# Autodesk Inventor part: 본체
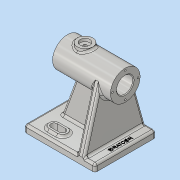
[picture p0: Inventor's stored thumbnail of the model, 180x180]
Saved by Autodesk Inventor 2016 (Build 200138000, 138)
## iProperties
Created: 2019-10
Part Number: 본체
Material: 알루미늄 6061
Document SubType Name: Modeling
Designer: Administrator
Density: 2.7 g/cm^3
Appearance: 알루미늄 - 평지
Mass: 588.046 g
Surface Area: 541.465 cm^2
Volume: 217.795 cm^3
Author: Administrator
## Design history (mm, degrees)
sketch "스케치1"
  geometry: L1 (-50, -43)-(50, -43); L2 (50, -43)-(50, 43); L3 (50, 43)-(-50, 43); L4 (-50, 43)-(-50, -43); L5 (-50, -43)-(50, 43); L6 (50, -43)-(-50, 43); 1 further point
  constraints: 12 end point, 2 midpoint, 2 parallel, 1 horizontal, 1 perpendicular
  dimensions: "d0" = 100 distance of L3.end L2.end; "d1" = 86 distance of L2.end L1.end
extrude "돌출1" new body sketch "스케치1" distance "d2" = 10; taper "d3" = 0 deg
sketch "스케치4"
  geometry: L1 (0, 0)-(0, 86) reference; C1 r 21 at (-86, 43); 2 further points
  constraints: 1 centre point, 1 horizontal alignment, 1 midpoint
  dimensions: "d8" = 42 diameter of C1; "d9" = 86 distance of point (0, 43) C1.centre
extrude "돌출2" join sketch "스케치4" distance "d10" = 82; taper "d11" = 0 deg
sketch "스케치5"
  geometry: L1 (32, 65)-(32, 107) reference; L2 (32, 86)-(-50, 86); L3 (-50, 65)-(-50, 107) reference; L4 (32, 100.5)-(-30, 100.5); L5 (-30, 100.5)-(-30, 97.5); L6 (-30, 97.5)-(-50, 97.5); L7 (-50, 97.5)-(-50, 86); L8 (32, 86)-(32, 100.5); 1 further point
  constraints: 12 end point, 3 perpendicular, 2 midpoint, 2 point on line, 1 collinear, 1 horizontal
  dimensions: "d12" = 29 diameter of L4 L2; "d13" = 23 diameter of L6 L2; "d14" = 62 distance between parallel lines of L5 L1
revolve "회전1" sketch "스케치5" stored, may be unused: angle "d15" = 90 deg
sketch "스케치6"
  geometry: 1 further point
node "작업 평면1"
sketch "스케치7"
  geometry: L1 (-32, 21)-(-32, -21) reference; C1 r 11 at (-7, 0); 1 further point
  constraints: 1 centre point, 1 horizontal alignment
  dimensions: "d17" = 22 diameter of C1; "d18" = 25 distance from line of C1.centre L1
extrude "돌출3" join sketch "스케치7" stored distance "d19" = 82; taper "d20" = 0 deg
sketch "스케치8"
  geometry: L1 (50, 10)-(-50, 10) reference; L2 (-50, 65)-(32, 65) reference; L3 (-50, 10)-(50, 10) reference; L4 (35, 10)-(13.589, 68.826); L5 (13.589, 68.826)-(-30, 68.826); L6 (-30, 68.826)-(-30, 10); L7 (-30, 10)-(35, 10); L8 (50, 0)-(50, 10) reference; 1 further point
  constraints: 8 end point, 2 point on line, 1 collinear, 1 horizontal, 1 perpendicular
  dimensions: "d21" = 15 distance from line of L4.start L8; "d22" = 70 deg angle of L1 L4; "d23" = 65 distance of L6.end L4.start; "d75" = 43.58899 distance of L4.end L5.end
extrude "돌출4" join sketch "스케치8" stored distance "d25" = 10; taper "d26" = 0 deg
node "작업 평면2"
sketch "스케치9"
  geometry: L1 (43, 10)-(-43, 10) reference; L2 (-43, 10)-(-20.228, 91.642); L3 (43, 10)-(20.228, 91.642); L4 (-43, 0)-(-43, 10) reference; L5 (-43, 10)-(43, 10); A1 r 21 centre (0, 86) between (-20.228, 91.642) and (20.228, 91.642) reference; A2 r 21 centre (0, 86) between (-20.228, 91.642) and (20.228, 91.642); 1 further point
  constraints: 6 end point, 4 point on circle, 4 tangent, 1 centre point, 1 perpendicular
extrude "돌출5" join sketch "스케치9" stored distance "d28" = 10; taper "d29" = 0 deg
sketch "스케치10" dims "d30" = 36
  geometry: A1 r 21 centre (0, 0) between (5.642, 20.228) and (5.642, -20.228) reference; 4 further points
  constraints: 2 horizontal alignment, 1 coincident, 2 other
hole "구멍1" sketch "스케치10" at (18, 0) diameter "d31" = 2.459; stored, may be unused: countersink angle "d35" = 90 deg, drill point angle "d37" = 118 deg; dims "d32" = 8, "d33" = 4, "d34" = 2, "d36" = 10
sketch "스케치11"
  geometry: C1 r 21 at (0, 0) reference; C2 r 18 at (0, 0); C3 r 1.23 at (-18, 0) reference; 2 further points
  constraints: 2 coincident, 1 centre point
  dimensions: "d41" = 36 diameter of C2
hole "구멍2" sketch "스케치11" at (-18, 0) diameter "d42" = 2.459; stored, may be unused: countersink angle "d46" = 90 deg, drill point angle "d48" = 118 deg; dims "d43" = 8, "d44" = 4, "d45" = 2, "d47" = 10
sketch "스케치12"
  geometry: L1 (-24, 27)-(-12, 27); L2 (-24, 20)-(-12, 20); L3 (-12, 34)-(-24, 34); L4 (-50, 43)-(-50, -43) reference; A1 r 7 centre (-24, 27) between (-24, 34) and (-24, 20); A2 r 7 centre (-12, 27) between (-12, 20) and (-12, 34); 2 further points
  constraints: 8 end point, 4 point on circle, 4 tangent, 2 centre point, 1 horizontal, 1 midpoint, 1 parallel
  dimensions: "d52" = 14 distance between parallel lines of L2 L3; "d54" = 12 distance of L1.end L1.start; "d55" = 26 distance from line of L1.start L4; "d56" = 27 vertical distance of point (0, 0) point (-18, 27)
extrude "돌출6" join sketch "스케치12" distance "d57" = 3; taper "d58" = 0 deg
sketch "스케치13"
  geometry: L1 (-12, 27)-(-24, 27); L2 (-12, 31.5)-(-24, 31.5); L3 (-24, 22.5)-(-12, 22.5); A1 r 7 centre (-24, 27) between (-24, 34) and (-24, 20) reference; A2 r 7 centre (-12, 27) between (-12, 20) and (-12, 34) reference; A3 r 4.5 centre (-12, 27) between (-12, 22.5) and (-12, 31.5); A4 r 4.5 centre (-24, 27) between (-24, 31.5) and (-24, 22.5); 2 further points
  constraints: 8 end point, 4 point on circle, 4 tangent, 2 centre point, 1 horizontal, 1 midpoint, 1 parallel
  dimensions: "d59" = 9 distance between parallel lines of L2 L3
extrude "돌출7" cut sketch "스케치13" stored distance "d60" = 3; taper "d61" = 0 deg
hole "구멍3" diameter "d64" = 4.917; stored, may be unused: countersink angle "d68" = 90 deg, drill point angle "d70" = 118 deg; dims "d62" = 10, "d63" = 10, "d65" = 12, "d66" = 14, "d67" = 4, "d69" = 17.1
sketch "스케치14"
  geometry: L1 (50, -43)-(50, 43) reference; L2 (-50, -43)-(50, -43) reference; 2 further points
  constraints: 1 other
  dimensions: "d71" = 7 distance from line of L1 point (43, 0); "d72" = 43 distance from line of L2 point (43, 0)
feature "엠보싱1" sketch "스케치14" dims "d12" = 29, "d13" = 23, "d14" = 62, "d73" = 0.5, "d74" = 0
fillet "모깎기1" dims "d76" = 3
fillet "모깎기2" dims "d77" = 3
fillet "모깎기3" dims "d78" = 3
fillet "모깎기4" dims "d79" = 3
fillet "모깎기5" dims "d80" = 3
fillet "모깎기6" dims "d81" = 3
fillet "모깎기7" dims "d82" = 3
fillet "모깎기8" dims "d83" = 3
chamfer "모따기1" distance "d84" = 1; stored, may be unused: second distance "d85" = 2, angle "d86" = 45 deg
chamfer "모따기2" distance "d87" = 1; stored, may be unused: second distance "d88" = 2, angle "d89" = 45 deg
feature "분할1"
node "솔리드1"
pattern_circular "원형 패턴1" dims angle "d39" = 360 deg
pattern_circular "원형 패턴2" dims angle "d50" = 360 deg
mirror "대칭1"
